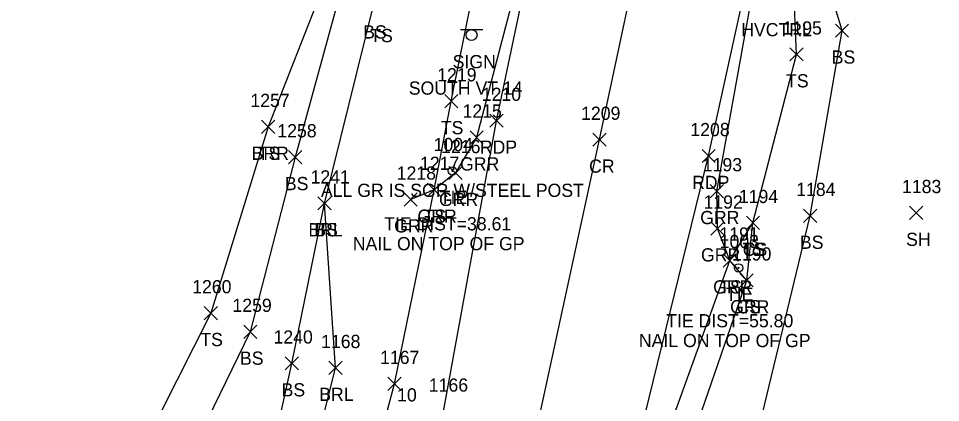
# Model space of a CAD drawing. Extents: x 1654425 to 1656893, y 667839 to 678429.
# Drawn here: x 1654499.7 to 1654639.3, y 668265.4 to 668323.6 of the extents above; entities that cross this region are included whole.
import ezdxf

# ---------------------------------------------------------------- set-up
doc = ezdxf.new("R2010")
doc.units = 0
for name, color, linetype in [('C_A', 7, 'Continuous'), ('C_C', 7, 'Continuous'), ('C_I', 7, 'Continuous'), ('CBP', 7, 'Continuous'), ('L_A', 7, 'Continuous'), ('L_I', 7, 'Continuous'), ('L_TIC', 7, 'Continuous'), ('LABL', 7, 'Continuous'), ('LELB', 7, 'Continuous'), ('P_A', 7, 'Continuous'), ('P_I', 7, 'Continuous'), ('P_TIC', 7, 'Continuous'), ('PET', 7, 'Continuous'), ('PRC', 7, 'Continuous'), ('R_A', 7, 'Continuous'), ('R_C', 7, 'Continuous'), ('R_I', 7, 'Continuous'), ('R_TIC', 7, 'Continuous'), ('RGR', 7, 'Continuous'), ('S_A', 7, 'Continuous'), ('S_C', 7, 'Continuous'), ('SSGN', 7, 'Continuous')]:
    doc.layers.add(name, color=color, linetype=linetype)

msp = doc.modelspace()

# ---------------------------------------------------------------- linework, layer by layer
at = {"layer": 'CBP'}
for centre, radius in [((1654565.41, 668300.47), 0.625), ((1654565.41, 668300.47), 0.0833), ((1654608.75, 668285.8), 0.625), ((1654608.75, 668285.8), 0.0833)]:
    msp.add_circle(centre, radius, dxfattribs=at)
at = {"layer": 'L_TIC'}
for points in [[(1654623.42, 668320.72), (1654625.42, 668322.72)], [(1654625.42, 668320.72), (1654623.42, 668322.72)], [(1654616.54, 668317.12), (1654618.54, 668319.12)], [(1654618.54, 668317.12), (1654616.54, 668319.12)], [(1654564.24, 668310.03), (1654566.24, 668312.03)], [(1654566.24, 668310.03), (1654564.24, 668312.03)], [(1654536.5, 668306.15), (1654538.5, 668308.15)], [(1654538.5, 668306.15), (1654536.5, 668308.15)], [(1654536.5, 668306.15), (1654538.5, 668308.15)], [(1654538.5, 668306.15), (1654536.5, 668308.15)], [(1654540.59, 668301.56), (1654542.59, 668303.56)], [(1654542.59, 668301.56), (1654540.59, 668303.56)], [(1654561.63, 668296.63), (1654563.63, 668298.63)], [(1654563.63, 668296.63), (1654561.63, 668298.63)], [(1654545.04, 668294.57), (1654547.04, 668296.57)], [(1654547.04, 668294.57), (1654545.04, 668296.57)], [(1654545.04, 668294.57), (1654547.04, 668296.57)], [(1654547.04, 668294.57), (1654545.04, 668296.57)], [(1654618.6, 668292.68), (1654620.6, 668294.68)], [(1654620.6, 668292.68), (1654618.6, 668294.68)], [(1654634.64, 668293.12), (1654636.64, 668295.12)], [(1654636.64, 668293.12), (1654634.64, 668295.12)], [(1654609.93, 668291.61), (1654611.93, 668293.61)], [(1654611.93, 668291.61), (1654609.93, 668293.61)], [(1654609.93, 668291.61), (1654611.93, 668293.61)], [(1654611.93, 668291.61), (1654609.93, 668293.61)], [(1654606.41, 668285.92), (1654608.41, 668287.92)], [(1654608.41, 668285.92), (1654606.41, 668287.92)], [(1654608.98, 668282.91), (1654610.98, 668284.91)], [(1654610.98, 668282.91), (1654608.98, 668284.91)], [(1654527.81, 668277.95), (1654529.81, 668279.95)], [(1654529.81, 668277.95), (1654527.81, 668279.95)], [(1654533.79, 668275.13), (1654535.79, 668277.13)], [(1654535.79, 668275.13), (1654533.79, 668277.13)], [(1654540.09, 668270.34), (1654542.09, 668272.34)], [(1654542.09, 668270.34), (1654540.09, 668272.34)], [(1654546.69, 668269.66), (1654548.69, 668271.66)], [(1654548.69, 668269.66), (1654546.69, 668271.66)], [(1654555.62, 668267.25), (1654557.62, 668269.25)], [(1654557.62, 668267.25), (1654555.62, 668269.25)]]:
    msp.add_lwpolyline(points, dxfattribs=at)
at = {"layer": 'LABL'}
for points in [[(1654560.74, 668356.68), (1654555.56, 668348.04), (1654549.18, 668336.9), (1654537.5, 668307.15)], [(1654516.35, 668119.35), (1654511.8, 668137.4), (1654522.79, 668181.51), (1654534.69, 668218.45), (1654547.69, 668270.66), (1654546.04, 668295.57)]]:
    msp.add_lwpolyline(points, dxfattribs=at)
at = {"layer": 'LELB'}
for points in [[(1654562.65, 668358.71), (1654556.85, 668347.4), (1654550.86, 668336.48), (1654541.59, 668302.56), (1654534.79, 668276.13), (1654518.99, 668243.67), (1654496.56, 668205), (1654493.42, 668170.69)], [(1654495.43, 667849.08), (1654500.81, 667895.96), (1654505.52, 667939.5), (1654510.36, 667978.52), (1654516.04, 668017.45), (1654520.13, 668047.02), (1654521.8, 668078.81), (1654520.96, 668117.25), (1654511.8, 668137.4), (1654509.93, 668148.4), (1654514.52, 668176.02), (1654523.2, 668207.52), (1654535.05, 668244.08), (1654541.09, 668271.34), (1654546.04, 668295.57), (1654553.44, 668325.52), (1654559.28, 668346.56), (1654565.49, 668358.45)], [(1654497.51, 667848.84), (1654501.99, 667895.85), (1654506.8, 667938.86), (1654511.52, 667978.38), (1654518.04, 668017.75), (1654522.23, 668046.7), (1654527.11, 668078.6), (1654529.66, 668139.05), (1654535.37, 668180.01), (1654543.78, 668219.73), (1654556.62, 668268.25), (1654562.63, 668297.63), (1654565.24, 668311.03), (1654570.38, 668336.59), (1654576.33, 668345.51)], [(1654532.88, 667846.44), (1654536.81, 667893.31), (1654541.08, 667931.05), (1654546.18, 667972.49), (1654551.95, 668011.91), (1654556.54, 668041.44), (1654561.5, 668072.5), (1654571.11, 668129.18), (1654578.93, 668172.43), (1654586.94, 668211.68), (1654595.67, 668254.34), (1654607.41, 668286.92), (1654610.93, 668292.61), (1654617.54, 668318.12), (1654616.79, 668336.32)], [(1654590.31, 668144.88), (1654595.35, 668170.77), (1654599.7, 668209.07), (1654610.68, 668256.65), (1654619.6, 668293.68), (1654624.42, 668321.72), (1654620.94, 668333.17)], [(1654537.5, 668307.15), (1654528.81, 668278.95), (1654513.38, 668248.35), (1654491, 668210.73), (1654483.31, 668171.64)], [(1654543.76, 667929.96), (1654549.41, 667971.89), (1654554.38, 668011.7), (1654559.28, 668041.03), (1654563.69, 668071.7), (1654573.34, 668128.44), (1654581.87, 668172.56), (1654590.31, 668210.74), (1654599.29, 668252.88), (1654609.98, 668283.91), (1654610.93, 668292.61)]]:
    msp.add_lwpolyline(points, dxfattribs=at)
at = {"layer": 'P_TIC'}
for points in [[(1654571.07, 668307.08), (1654573.07, 668309.08)], [(1654573.07, 668307.08), (1654571.07, 668309.08)], [(1654586.68, 668304.21), (1654588.68, 668306.21)], [(1654588.68, 668304.21), (1654586.68, 668306.21)], [(1654603.22, 668301.74), (1654605.22, 668303.74)], [(1654605.22, 668301.74), (1654603.22, 668303.74)]]:
    msp.add_lwpolyline(points, dxfattribs=at)
at = {"layer": 'PET'}
for points in [[(1654500.93, 667848.14), (1654504.78, 667896.02), (1654509.67, 667937.82), (1654515.37, 667977.68), (1654521.39, 668016.85), (1654525.99, 668046.3), (1654531.26, 668078.24), (1654541.38, 668136.51), (1654548.54, 668178.15), (1654556.41, 668219.5), (1654564.06, 668264.06), (1654572.07, 668308.08), (1654579.91, 668345.23), (1654595.42, 668341.51), (1654611.88, 668337.75)], [(1654528.99, 667846.47), (1654531.96, 667893.38), (1654537.26, 667931.97), (1654542.41, 667973.09), (1654548.22, 668012.23), (1654553.01, 668041.79), (1654558.55, 668073.69), (1654568.05, 668129.99), (1654575.97, 668172.91), (1654583.21, 668212.31), (1654592.64, 668255.65), (1654604.22, 668302.74), (1654611.88, 668337.75)]]:
    msp.add_lwpolyline(points, dxfattribs=at)
at = {"layer": 'PRC'}
msp.add_lwpolyline([(1654514.39, 667847.42), (1654517.73, 667895.01), (1654522.68, 667935.26), (1654527.79, 667975.85), (1654533.53, 668014.87), (1654538.36, 668044.09), (1654543.94, 668076.54), (1654553.86, 668133.31), (1654561.61, 668175.74), (1654568.95, 668214.62), (1654577.86, 668259.83), (1654587.68, 668305.21), (1654595.42, 668341.51)], dxfattribs=at)
at = {"layer": 'R_TIC'}
for points in [[(1654568.07, 668304.54), (1654570.07, 668306.54)], [(1654570.07, 668304.54), (1654568.07, 668306.54)], [(1654564.88, 668299.17), (1654566.88, 668301.17)], [(1654566.88, 668299.17), (1654564.88, 668301.17)], [(1654561.63, 668296.63), (1654563.63, 668298.63)], [(1654563.63, 668296.63), (1654561.63, 668298.63)], [(1654604.45, 668296.42), (1654606.45, 668298.42)], [(1654606.45, 668296.42), (1654604.45, 668298.42)], [(1654558.09, 668295.16), (1654560.09, 668297.16)], [(1654560.09, 668295.16), (1654558.09, 668297.16)], [(1654604.57, 668290.77), (1654606.57, 668292.77)], [(1654606.57, 668290.77), (1654604.57, 668292.77)], [(1654606.41, 668285.92), (1654608.41, 668287.92)], [(1654608.41, 668285.92), (1654606.41, 668287.92)], [(1654608.98, 668282.91), (1654610.98, 668284.91)], [(1654610.98, 668282.91), (1654608.98, 668284.91)]]:
    msp.add_lwpolyline(points, dxfattribs=at)
at = {"layer": 'RGR'}
for points in [[(1654579.2, 668344.31), (1654569.07, 668305.54), (1654565.88, 668300.17), (1654562.63, 668297.63), (1654559.09, 668296.16)], [(1654609.98, 668283.91), (1654607.41, 668286.92), (1654605.57, 668291.77), (1654605.45, 668297.42), (1654612.62, 668337.22)]]:
    msp.add_lwpolyline(points, dxfattribs=at)
at = {"layer": 'SSGN'}
for p, q in [((1654566.65, 668321.88), (1654569.99, 668321.88)), ((1654568.3, 668321.04), (1654568.3, 668321.04))]:
    msp.add_line(p, q, dxfattribs=at)
msp.add_circle((1654568.3, 668321.04), 0.833, dxfattribs=at)

# ---------------------------------------------------------------- texts
at = {"layer": 'C_A'}
for s, p in [('HVCTRL', (1654609.15, 668320.86)), ('TIE', (1654563.49, 668295.47)), ('TIE', (1654606.82, 668280.8))]:
    msp.add_text(s, height=2, dxfattribs=at).set_placement(p)
at = {"layer": 'C_C'}
for s, p in [('TIE DIST=38.61', (1654555.06, 668291.47)), ('NAIL ON TOP OF GP', (1654550.32, 668288.47)), ('TIE DIST=55.80', (1654597.79, 668276.8)), ('NAIL ON TOP OF GP', (1654593.65, 668273.8))]:
    msp.add_text(s, height=2, dxfattribs=at).set_placement(p)
at = {"layer": 'C_I'}
for s, p in [('1004', (1654562.56, 668303.47)), ('1003', (1654605.89, 668288.8)), ('10', (1654557.03, 668265.57))]:
    msp.add_text(s, height=2, dxfattribs=at).set_placement(p)
at = {"layer": 'L_A'}
for s, p in [('BS', (1654551.89, 668320.52)), ('TS', (1654552.96, 668319.97)), ('BS', (1654622.86, 668316.72)), ('TS', (1654615.95, 668313.12)), ('TS', (1654563.65, 668306.03)), ('BRR', (1654534.99, 668302.15)), ('TS', (1654535.91, 668302.15)), ('BS', (1654540.03, 668297.56)), ('TS', (1654561.04, 668292.63)), ('BRL', (1654543.59, 668290.57)), ('BS', (1654544.48, 668290.57)), ('BS', (1654618.05, 668288.68)), ('SH', (1654634.13, 668289.12)), ('TS', (1654609.34, 668287.61)), ('CS', (1654609.37, 668287.61)), ('TS', (1654605.82, 668281.92)), ('CS', (1654608.43, 668278.91)), ('TS', (1654527.22, 668273.95)), ('BS', (1654533.23, 668271.13)), ('BS', (1654539.53, 668266.34)), ('BRL', (1654545.23, 668265.66))]:
    msp.add_text(s, height=2, dxfattribs=at).set_placement(p)
at = {"layer": 'L_I'}
for s, p in [('1195', (1654615.42, 668321.12)), ('1219', (1654563.11, 668314.03)), ('1257', (1654534.81, 668310.15)), ('1257', (1654534.81, 668310.15)), ('1258', (1654538.89, 668305.56)), ('1217', (1654560.5, 668300.63)), ('1241', (1654543.92, 668298.57)), ('1241', (1654543.92, 668298.57)), ('1183', (1654633.51, 668297.12)), ('1194', (1654608.8, 668295.61)), ('1194', (1654608.8, 668295.61)), ('1184', (1654617.48, 668296.68)), ('1191', (1654605.85, 668289.92)), ('1190', (1654607.77, 668286.91)), ('1260', (1654525.99, 668281.95)), ('1259', (1654532.09, 668279.13)), ('1240', (1654538.31, 668274.34)), ('1168', (1654545.52, 668273.66)), ('1167', (1654554.45, 668271.25))]:
    msp.add_text(s, height=2, dxfattribs=at).set_placement(p)
at = {"layer": 'P_A'}
for s, p in [('RDP', (1654569.56, 668303.08)), ('CR', (1654586.11, 668300.21)), ('RDP', (1654601.71, 668297.74))]:
    msp.add_text(s, height=2, dxfattribs=at).set_placement(p)
at = {"layer": 'P_I'}
for s, p in [('1210', (1654569.86, 668311.08)), ('1209', (1654584.9, 668308.21)), ('1208', (1654601.45, 668305.74)), ('1166', (1654561.83, 668267.06))]:
    msp.add_text(s, height=2, dxfattribs=at).set_placement(p)
at = {"layer": 'R_A'}
for p in [(1654566.56, 668300.54), (1654563.37, 668295.17), (1654560.12, 668292.63), (1654602.94, 668292.42), (1654556.58, 668291.16), (1654603.06, 668286.77), (1654604.9, 668281.92), (1654607.47, 668278.91)]:
    msp.add_text('GRR', height=2, dxfattribs=at).set_placement(p)
at = {"layer": 'R_C'}
msp.add_text('ALL GR IS SGR W/STEEL POST', height=2, dxfattribs=at).set_placement((1654545.49, 668296.54))
at = {"layer": 'R_I'}
for s, p in [('1215', (1654566.94, 668308.54)), ('1216', (1654563.7, 668303.17)), ('1217', (1654560.5, 668300.63)), ('1193', (1654603.33, 668300.42)), ('1218', (1654556.97, 668299.16)), ('1192', (1654603.44, 668294.77)), ('1191', (1654605.85, 668289.92)), ('1190', (1654607.77, 668286.91))]:
    msp.add_text(s, height=2, dxfattribs=at).set_placement(p)
at = {"layer": 'S_A'}
msp.add_text('SIGN', height=2, dxfattribs=at).set_placement((1654565.44, 668316.02))
at = {"layer": 'S_C'}
msp.add_text('SOUTH VT 14', height=2, dxfattribs=at).set_placement((1654558.8, 668312.02))

doc.saveas('drawing.dxf')
